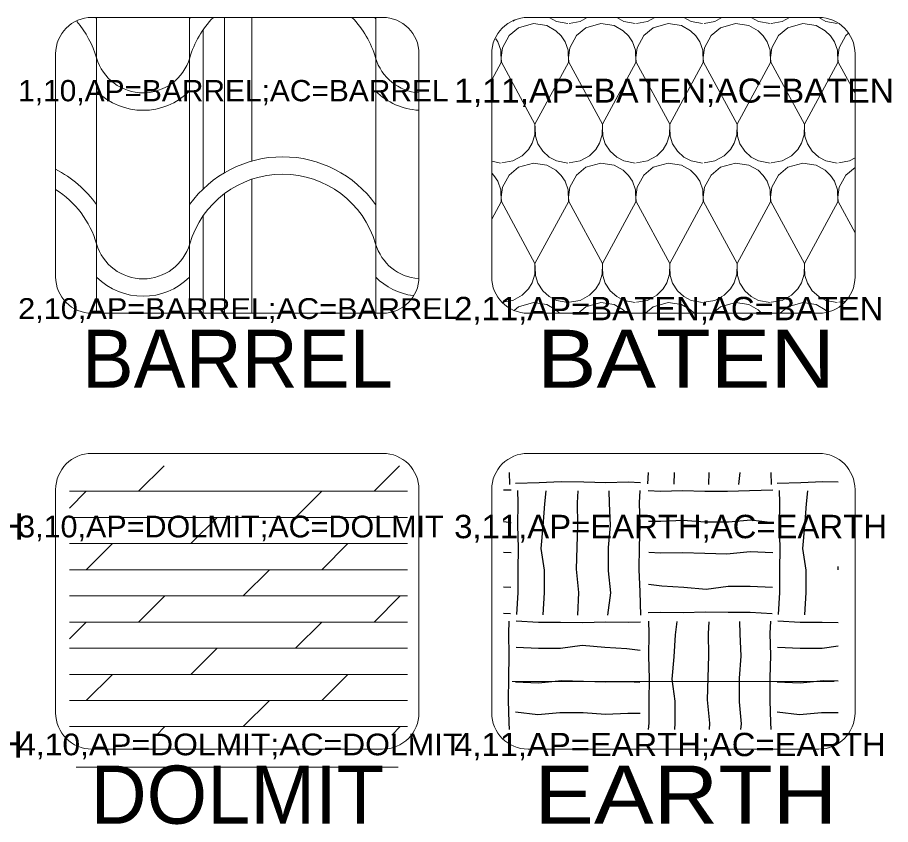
# Model space of a CAD drawing. Extents: x 95935 to 95946.4, y 95971.2 to 95974.7.
# Drawn here: x 95940.433 to 95941.635, y 95973.621 to 95974.732 of the extents above; entities that cross this region are included whole.
import ezdxf
from ezdxf.enums import TextEntityAlignment as Align

# ---------------------------------------------------------------- set-up
doc = ezdxf.new("R2010")
doc.units = 0
doc.header["$LTSCALE"] = 0.013
for name, color, linetype, lineweight in [('1', 7, 'Continuous', 13), ('25', 7, 'Continuous', 13), ('6', 7, 'Continuous', 13), ('63', 7, 'Continuous', 13)]:
    doc.layers.add(name, color=color, linetype=linetype, lineweight=lineweight)
doc.layers.add('20', color=7, linetype='Continuous')

msp = doc.modelspace()

# ---------------------------------------------------------------- linework, layer by layer
at = {"layer": '1'}
for p, q in [((95940.5357, 95974.7318), (95940.9357, 95974.7318)), ((95941.1357, 95974.7318), (95941.5357, 95974.7318)), ((95940.4857, 95974.3747), (95940.4857, 95974.6818)), ((95940.9857, 95974.6818), (95940.9857, 95974.3747)), ((95941.0857, 95974.3747), (95941.0857, 95974.6818)), ((95941.5857, 95974.6818), (95941.5857, 95974.3747)), ((95940.9357, 95974.3247), (95940.5357, 95974.3247)), ((95941.5357, 95974.3247), (95941.1357, 95974.3247)), ((95940.5357, 95974.1318), (95940.9357, 95974.1318)), ((95941.1357, 95974.1318), (95941.5357, 95974.1318)), ((95940.4857, 95973.7747), (95940.4857, 95974.0818)), ((95940.9857, 95974.0818), (95940.9857, 95973.7747)), ((95941.0857, 95973.7747), (95941.0857, 95974.0818)), ((95941.5857, 95974.0818), (95941.5857, 95973.7747)), ((95940.9357, 95973.7247), (95940.5357, 95973.7247)), ((95941.5357, 95973.7247), (95941.1357, 95973.7247))]:
    msp.add_line(p, q, dxfattribs=at)
for centre, start, end in [((95940.5357, 95974.6818), 90, 180), ((95940.9357, 95974.6818), 0, 90), ((95941.1357, 95974.6818), 90, 180), ((95941.5357, 95974.6818), 0, 90), ((95940.5357, 95974.3747), 180, 270), ((95940.9357, 95974.3747), 270, 0), ((95941.1357, 95974.3747), 180, 270), ((95941.5357, 95974.3747), 270, 0), ((95940.5357, 95974.0818), 90, 180), ((95940.9357, 95974.0818), 0, 90), ((95941.1357, 95974.0818), 90, 180), ((95941.5357, 95974.0818), 0, 90), ((95940.5357, 95973.7747), 180, 270), ((95940.9357, 95973.7747), 270, 0), ((95941.1357, 95973.7747), 180, 270), ((95941.5357, 95973.7747), 270, 0)]:
    msp.add_arc(centre, 0.05, start, end, dxfattribs=at)
at = {"layer": '25'}
for p, q in [((95941.5569, 95973.8178), (95941.1141, 95973.8178)), ((95940.9569, 95973.6997), (95940.5141, 95973.6997))]:
    msp.add_line(p, q, dxfattribs=at)
at = {"layer": '6'}
for p, q in [((95940.5421, 95974.348), (95940.5421, 95974.7318)), ((95940.6701, 95974.348), (95940.6701, 95974.7318)), ((95940.7181, 95974.5181), (95940.7181, 95974.7318)), ((95940.7559, 95974.5342), (95940.7559, 95974.7318)), ((95940.9261, 95974.348), (95940.9261, 95974.7318)), ((95941.1184, 95974.7284), (95941.1152, 95974.7266)), ((95940.6885, 95974.4955), (95940.6885, 95974.7146)), ((95941.098, 95974.5314), (95941.0857, 95974.5338)), ((95940.7559, 95974.348), (95940.7559, 95974.5092)), ((95940.7181, 95974.348), (95940.7181, 95974.4893)), ((95940.6885, 95974.348), (95940.6885, 95974.4586)), ((95940.5421, 95974.3247), (95940.5421, 95974.348)), ((95940.6701, 95974.3247), (95940.6701, 95974.348)), ((95940.6885, 95974.3247), (95940.6885, 95974.348)), ((95940.7181, 95974.3247), (95940.7181, 95974.348)), ((95940.7559, 95974.3247), (95940.7559, 95974.348)), ((95940.9261, 95974.3247), (95940.9261, 95974.348)), ((95941.5725, 95974.3414), (95941.5632, 95974.3397)), ((95940.5999, 95974.0796), (95940.6349, 95974.1146)), ((95940.9239, 95974.0796), (95940.9589, 95974.1146)), ((95940.5048, 95974.0796), (95940.97, 95974.0796)), ((95940.5048, 95974.0565), (95940.5279, 95974.0796)), ((95940.8159, 95974.0436), (95940.8519, 95974.0796)), ((95940.5048, 95974.0436), (95940.97, 95974.0436)), ((95940.5048, 95974.0436), (95940.97, 95974.0436)), ((95940.6719, 95974.0076), (95940.7079, 95974.0436)), ((95940.5048, 95974.0076), (95940.97, 95974.0076)), ((95940.5279, 95973.9716), (95940.5639, 95974.0076)), ((95940.8519, 95973.9716), (95940.8879, 95974.0076)), ((95940.5048, 95973.9716), (95940.97, 95973.9716)), ((95940.7439, 95973.9356), (95940.7799, 95973.9716)), ((95940.5048, 95973.9356), (95940.97, 95973.9356)), ((95940.5999, 95973.8996), (95940.6359, 95973.9356)), ((95940.9239, 95973.8996), (95940.9599, 95973.9356)), ((95940.5048, 95973.8996), (95940.97, 95973.8996)), ((95940.5048, 95973.8765), (95940.5279, 95973.8996)), ((95940.8159, 95973.8636), (95940.8519, 95973.8996)), ((95940.5048, 95973.8636), (95940.97, 95973.8636)), ((95940.5048, 95973.8636), (95940.97, 95973.8636)), ((95940.6719, 95973.8276), (95940.7079, 95973.8636)), ((95940.5048, 95973.8276), (95940.97, 95973.8276)), ((95940.5279, 95973.7916), (95940.5639, 95973.8276)), ((95940.8519, 95973.7916), (95940.8879, 95973.8276)), ((95940.5048, 95973.7916), (95940.97, 95973.7916)), ((95940.7439, 95973.7556), (95940.7799, 95973.7916)), ((95940.5048, 95973.7556), (95940.97, 95973.7556)), ((95940.6243, 95973.744), (95940.6359, 95973.7556)), ((95940.9483, 95973.744), (95940.9599, 95973.7556))]:
    msp.add_line(p, q, dxfattribs=at)
at = {"layer": '6', "lineweight": 25}
for p, q in [((95941.1109, 95974.0891), (95941.1104, 95974.1056)), ((95941.3005, 95974.09), (95941.3014, 95974.1056)), ((95941.3366, 95974.0896), (95941.3375, 95974.1056)), ((95941.3844, 95974.0891), (95941.3851, 95974.1056)), ((95941.4257, 95974.0891), (95941.4278, 95974.1056)), ((95941.4709, 95974.0891), (95941.4704, 95974.1056)), ((95941.1127, 95974.0813), (95941.102, 95974.081)), ((95941.1127, 95974.0361), (95941.102, 95974.0375)), ((95941.1127, 95973.9948), (95941.102, 95973.9952)), ((95941.1122, 95973.947), (95941.102, 95973.9476)), ((95941.1118, 95973.9109), (95941.102, 95973.9114))]:
    msp.add_line(p, q, dxfattribs=at)
at = {"layer": '6'}
for points in [[(95941.1907, 95974.7234), (95941.175, 95974.7264), (95941.165, 95974.7316), (95941.1648, 95974.7318)], [(95941.2173, 95974.7318), (95941.2075, 95974.7264), (95941.1925, 95974.7237)], [(95941.2833, 95974.7234), (95941.2676, 95974.7264), (95941.2577, 95974.7316), (95941.2575, 95974.7318)], [(95941.31, 95974.7318), (95941.3002, 95974.7264), (95941.2852, 95974.7237)], [(95941.376, 95974.7234), (95941.3603, 95974.7264), (95941.3503, 95974.7316), (95941.3501, 95974.7318)], [(95941.4026, 95974.7318), (95941.3928, 95974.7264), (95941.3779, 95974.7237)], [(95941.4687, 95974.7234), (95941.453, 95974.7264), (95941.443, 95974.7316), (95941.4428, 95974.7318)], [(95941.4953, 95974.7318), (95941.4855, 95974.7264), (95941.4705, 95974.7237)], [(95941.5613, 95974.7234), (95941.5456, 95974.7264), (95941.5357, 95974.7316), (95941.5355, 95974.7318)], [(95941.1907, 95974.5314), (95941.175, 95974.5344), (95941.165, 95974.5396), (95941.156, 95974.5477), (95941.1494, 95974.5579), (95941.1458, 95974.5684), (95941.1457, 95974.5802), (95941.1453, 95974.5849), (95941.1914, 95974.67), (95941.1909, 95974.6866), (95941.1867, 95974.6983), (95941.1814, 95974.7063), (95941.1742, 95974.7134), (95941.1615, 95974.7206), (95941.1431, 95974.7234), (95941.1225, 95974.7175), (95941.1096, 95974.7068), (95941.1006, 95974.6902), (95941.0987, 95974.6766), (95941.0992, 95974.6703), (95941.1453, 95974.5849), (95941.1451, 95974.5703), (95941.1413, 95974.5586), (95941.1363, 95974.5502), (95941.1275, 95974.5414), (95941.1148, 95974.5344), (95941.0999, 95974.5317)], [(95941.2833, 95974.5314), (95941.2676, 95974.5344), (95941.2577, 95974.5396), (95941.2487, 95974.5477), (95941.2421, 95974.5579), (95941.2385, 95974.5684), (95941.2383, 95974.5802), (95941.238, 95974.5849), (95941.284, 95974.67), (95941.2835, 95974.6866), (95941.2793, 95974.6983), (95941.274, 95974.7063), (95941.2668, 95974.7134), (95941.2542, 95974.7206), (95941.2358, 95974.7234), (95941.2152, 95974.7175), (95941.2022, 95974.7068), (95941.1933, 95974.6902), (95941.1914, 95974.6766), (95941.1918, 95974.6703), (95941.238, 95974.5849), (95941.2378, 95974.5703), (95941.234, 95974.5586), (95941.2289, 95974.5502), (95941.2202, 95974.5414), (95941.2075, 95974.5344), (95941.1925, 95974.5317)], [(95941.376, 95974.5314), (95941.3603, 95974.5344), (95941.3503, 95974.5396), (95941.3414, 95974.5477), (95941.3347, 95974.5579), (95941.3312, 95974.5684), (95941.331, 95974.5802), (95941.3307, 95974.5849), (95941.3767, 95974.67), (95941.3762, 95974.6866), (95941.372, 95974.6983), (95941.3667, 95974.7063), (95941.3595, 95974.7134), (95941.3469, 95974.7206), (95941.3285, 95974.7234), (95941.3079, 95974.7175), (95941.2949, 95974.7068), (95941.286, 95974.6902), (95941.284, 95974.6766), (95941.2845, 95974.6703), (95941.3307, 95974.5849), (95941.3304, 95974.5703), (95941.3267, 95974.5586), (95941.3216, 95974.5502), (95941.3129, 95974.5414), (95941.3002, 95974.5344), (95941.2852, 95974.5317)], [(95941.4687, 95974.5314), (95941.453, 95974.5344), (95941.443, 95974.5396), (95941.4341, 95974.5477), (95941.4274, 95974.5579), (95941.4238, 95974.5684), (95941.4237, 95974.5802), (95941.4233, 95974.5849), (95941.4694, 95974.67), (95941.4689, 95974.6866), (95941.4647, 95974.6983), (95941.4594, 95974.7063), (95941.4522, 95974.7134), (95941.4395, 95974.7206), (95941.4211, 95974.7234), (95941.4005, 95974.7175), (95941.3876, 95974.7068), (95941.3786, 95974.6902), (95941.3767, 95974.6766), (95941.3772, 95974.6703), (95941.4233, 95974.5849), (95941.4231, 95974.5703), (95941.4193, 95974.5586), (95941.4143, 95974.5502), (95941.4055, 95974.5414), (95941.3928, 95974.5344), (95941.3779, 95974.5317)], [(95941.5613, 95974.5314), (95941.5456, 95974.5344), (95941.5357, 95974.5396), (95941.5267, 95974.5477), (95941.5201, 95974.5579), (95941.5165, 95974.5684), (95941.5163, 95974.5802), (95941.516, 95974.5849), (95941.562, 95974.67), (95941.5615, 95974.6866), (95941.5573, 95974.6983), (95941.552, 95974.7063), (95941.5448, 95974.7134), (95941.5322, 95974.7206), (95941.5138, 95974.7234), (95941.4932, 95974.7175), (95941.4802, 95974.7068), (95941.4713, 95974.6902), (95941.4694, 95974.6766), (95941.4698, 95974.6703), (95941.516, 95974.5849), (95941.5158, 95974.5703), (95941.512, 95974.5586), (95941.5069, 95974.5502), (95941.4982, 95974.5414), (95941.4855, 95974.5344), (95941.4705, 95974.5317)], [(95941.0857, 95974.646), (95941.0987, 95974.67), (95941.0982, 95974.6866), (95941.094, 95974.6983), (95941.0912, 95974.7026)], [(95941.5762, 95974.7095), (95941.5729, 95974.7068), (95941.564, 95974.6902), (95941.562, 95974.6766), (95941.5625, 95974.6703), (95941.5857, 95974.6274)], [(95941.5857, 95974.5385), (95941.5782, 95974.5344), (95941.5632, 95974.5317)], [(95941.1907, 95974.3394), (95941.175, 95974.3424), (95941.165, 95974.3476), (95941.156, 95974.3557), (95941.1494, 95974.3659), (95941.1458, 95974.3764), (95941.1457, 95974.3882), (95941.1453, 95974.3929), (95941.1914, 95974.478), (95941.1909, 95974.4946), (95941.1867, 95974.5063), (95941.1814, 95974.5143), (95941.1742, 95974.5214), (95941.1615, 95974.5286), (95941.1431, 95974.5314), (95941.1225, 95974.5255), (95941.1096, 95974.5148), (95941.1006, 95974.4982), (95941.0987, 95974.4846), (95941.0992, 95974.4783), (95941.1453, 95974.3929), (95941.1451, 95974.3783), (95941.1413, 95974.3666), (95941.1363, 95974.3582), (95941.1275, 95974.3494), (95941.1148, 95974.3424), (95941.0999, 95974.3397)], [(95941.2833, 95974.3394), (95941.2676, 95974.3424), (95941.2577, 95974.3476), (95941.2487, 95974.3557), (95941.2421, 95974.3659), (95941.2385, 95974.3764), (95941.2383, 95974.3882), (95941.238, 95974.3929), (95941.284, 95974.478), (95941.2835, 95974.4946), (95941.2793, 95974.5063), (95941.274, 95974.5143), (95941.2668, 95974.5214), (95941.2542, 95974.5286), (95941.2358, 95974.5314), (95941.2152, 95974.5255), (95941.2022, 95974.5148), (95941.1933, 95974.4982), (95941.1914, 95974.4846), (95941.1918, 95974.4783), (95941.238, 95974.3929), (95941.2378, 95974.3783), (95941.234, 95974.3666), (95941.2289, 95974.3582), (95941.2202, 95974.3494), (95941.2075, 95974.3424), (95941.1925, 95974.3397)], [(95941.376, 95974.3394), (95941.3603, 95974.3424), (95941.3503, 95974.3476), (95941.3414, 95974.3557), (95941.3347, 95974.3659), (95941.3312, 95974.3764), (95941.331, 95974.3882), (95941.3307, 95974.3929), (95941.3767, 95974.478), (95941.3762, 95974.4946), (95941.372, 95974.5063), (95941.3667, 95974.5143), (95941.3595, 95974.5214), (95941.3469, 95974.5286), (95941.3285, 95974.5314), (95941.3079, 95974.5255), (95941.2949, 95974.5148), (95941.286, 95974.4982), (95941.284, 95974.4846), (95941.2845, 95974.4783), (95941.3307, 95974.3929), (95941.3304, 95974.3783), (95941.3267, 95974.3666), (95941.3216, 95974.3582), (95941.3129, 95974.3494), (95941.3002, 95974.3424), (95941.2852, 95974.3397)], [(95941.4687, 95974.3394), (95941.453, 95974.3424), (95941.443, 95974.3476), (95941.4341, 95974.3557), (95941.4274, 95974.3659), (95941.4238, 95974.3764), (95941.4237, 95974.3882), (95941.4233, 95974.3929), (95941.4694, 95974.478), (95941.4689, 95974.4946), (95941.4647, 95974.5063), (95941.4594, 95974.5143), (95941.4522, 95974.5214), (95941.4395, 95974.5286), (95941.4211, 95974.5314), (95941.4005, 95974.5255), (95941.3876, 95974.5148), (95941.3786, 95974.4982), (95941.3767, 95974.4846), (95941.3772, 95974.4783), (95941.4233, 95974.3929), (95941.4231, 95974.3783), (95941.4193, 95974.3666), (95941.4143, 95974.3582), (95941.4055, 95974.3494), (95941.3928, 95974.3424), (95941.3779, 95974.3397)], [(95941.5613, 95974.3394), (95941.5456, 95974.3424), (95941.5357, 95974.3476), (95941.5267, 95974.3557), (95941.5201, 95974.3659), (95941.5165, 95974.3764), (95941.5163, 95974.3882), (95941.516, 95974.3929), (95941.562, 95974.478), (95941.5615, 95974.4946), (95941.5573, 95974.5063), (95941.552, 95974.5143), (95941.5448, 95974.5214), (95941.5322, 95974.5286), (95941.5138, 95974.5314), (95941.4932, 95974.5255), (95941.4802, 95974.5148), (95941.4713, 95974.4982), (95941.4694, 95974.4846), (95941.4698, 95974.4783), (95941.516, 95974.3929), (95941.5158, 95974.3783), (95941.512, 95974.3666), (95941.5069, 95974.3582), (95941.4982, 95974.3494), (95941.4855, 95974.3424), (95941.4705, 95974.3397)], [(95941.5857, 95974.5253), (95941.5729, 95974.5148), (95941.564, 95974.4982), (95941.562, 95974.4846), (95941.5625, 95974.4783), (95941.5857, 95974.4354)], [(95941.0857, 95974.454), (95941.0987, 95974.478), (95941.0982, 95974.4946), (95941.094, 95974.5063), (95941.0887, 95974.5143), (95941.0857, 95974.5173)], [(95941.179, 95974.3247), (95941.1742, 95974.3294), (95941.1615, 95974.3366), (95941.1431, 95974.3394), (95941.1225, 95974.3335), (95941.1165, 95974.3285)], [(95941.2716, 95974.3247), (95941.2668, 95974.3294), (95941.2542, 95974.3366), (95941.2358, 95974.3394), (95941.2152, 95974.3335), (95941.2045, 95974.3247)], [(95941.3643, 95974.3247), (95941.3595, 95974.3294), (95941.3469, 95974.3366), (95941.3285, 95974.3394), (95941.3079, 95974.3335), (95941.2972, 95974.3247)], [(95941.457, 95974.3247), (95941.4522, 95974.3294), (95941.4395, 95974.3366), (95941.4211, 95974.3394), (95941.4005, 95974.3335), (95941.3899, 95974.3247)], [(95941.5472, 95974.327), (95941.5448, 95974.3294), (95941.5322, 95974.3366), (95941.5138, 95974.3394), (95941.4932, 95974.3335), (95941.4825, 95974.3247)]]:
    msp.add_lwpolyline(points, dxfattribs=at)
at = {"layer": '6', "lineweight": 25}
for points in [[(95941.1187, 95974.0909), (95941.1509, 95974.0918), (95941.1813, 95974.0931), (95941.2126, 95974.0927), (95941.243, 95974.0918), (95941.2735, 95974.0927), (95941.2904, 95974.0918)], [(95941.4787, 95974.0909), (95941.5109, 95974.0918), (95941.5413, 95974.0931), (95941.5627, 95974.0928)], [(95941.1205, 95973.91), (95941.1222, 95973.9404), (95941.1222, 95973.9709), (95941.1227, 95974.0017), (95941.1218, 95974.0326), (95941.1222, 95974.0639), (95941.1218, 95974.0808)], [(95941.1566, 95973.9096), (95941.1583, 95973.9404), (95941.1583, 95973.9709), (95941.154, 95974.0008), (95941.1566, 95974.0317), (95941.1587, 95974.0621), (95941.1609, 95974.0804)], [(95941.2044, 95973.9091), (95941.2057, 95973.9404), (95941.2026, 95973.9726), (95941.2035, 95974.0026), (95941.2044, 95974.0334), (95941.2039, 95974.0639), (95941.2048, 95974.08)], [(95941.2457, 95973.9091), (95941.2496, 95973.9396), (95941.2465, 95973.97), (95941.2465, 95974.0022), (95941.2491, 95974.0326), (95941.2478, 95974.0634), (95941.2474, 95974.0804)], [(95941.2909, 95973.9091), (95941.29, 95973.9413), (95941.2887, 95973.9717), (95941.2891, 95974.003), (95941.29, 95974.0334), (95941.2891, 95974.0639), (95941.29, 95974.0808)], [(95941.4727, 95974.0813), (95941.4405, 95974.0804), (95941.4101, 95974.0791), (95941.3788, 95974.0795), (95941.3484, 95974.0804), (95941.3179, 95974.0795), (95941.301, 95974.0804)], [(95941.4805, 95973.91), (95941.4822, 95973.9404), (95941.4822, 95973.9709), (95941.4827, 95974.0017), (95941.4818, 95974.0326), (95941.4822, 95974.0639), (95941.4818, 95974.0808)], [(95941.5166, 95973.9096), (95941.5183, 95973.9404), (95941.5183, 95973.9709), (95941.514, 95974.0008), (95941.5166, 95974.0317), (95941.5187, 95974.0621), (95941.5209, 95974.0804)], [(95941.4727, 95974.0361), (95941.4422, 95974.04), (95941.4118, 95974.0369), (95941.3796, 95974.0369), (95941.3492, 95974.0395), (95941.3184, 95974.0382), (95941.3014, 95974.0378)], [(95941.4727, 95973.9948), (95941.4414, 95973.9961), (95941.4092, 95973.993), (95941.3792, 95973.9939), (95941.3484, 95973.9948), (95941.3179, 95973.9943), (95941.3019, 95973.9952)], [(95941.5627, 95973.9716), (95941.5626, 95973.9726), (95941.5627, 95973.9759)], [(95941.4722, 95973.947), (95941.4414, 95973.9487), (95941.4109, 95973.9487), (95941.381, 95973.9444), (95941.3501, 95973.947), (95941.3197, 95973.9491), (95941.3014, 95973.9513)], [(95941.4718, 95973.9109), (95941.4414, 95973.9126), (95941.4109, 95973.9126), (95941.3801, 95973.9131), (95941.3492, 95973.9122), (95941.3179, 95973.9126), (95941.301, 95973.9122)], [(95941.1103, 95973.7517), (95941.11, 95973.7613), (95941.1087, 95973.7917), (95941.1091, 95973.823), (95941.11, 95973.8534), (95941.1091, 95973.8839), (95941.11, 95973.9008)], [(95941.1196, 95973.9013), (95941.15, 95973.8996), (95941.1805, 95973.8996), (95941.2113, 95973.8991), (95941.2422, 95973.9), (95941.2735, 95973.8996), (95941.2904, 95973.9)], [(95941.3017, 95973.7517), (95941.3022, 95973.7604), (95941.3022, 95973.7909), (95941.3027, 95973.8217), (95941.3018, 95973.8526), (95941.3022, 95973.8839), (95941.3018, 95973.9008)], [(95941.3378, 95973.7517), (95941.3383, 95973.7604), (95941.3383, 95973.7909), (95941.334, 95973.8208), (95941.3366, 95973.8517), (95941.3387, 95973.8821), (95941.3409, 95973.9004)], [(95941.3853, 95973.7517), (95941.3857, 95973.7604), (95941.3826, 95973.7926), (95941.3835, 95973.8226), (95941.3844, 95973.8534), (95941.3839, 95973.8839), (95941.3848, 95973.9)], [(95941.4286, 95973.7517), (95941.4296, 95973.7596), (95941.4265, 95973.79), (95941.4265, 95973.8222), (95941.4291, 95973.8526), (95941.4278, 95973.8834), (95941.4274, 95973.9004)], [(95941.4703, 95973.7517), (95941.47, 95973.7613), (95941.4687, 95973.7917), (95941.4691, 95973.823), (95941.47, 95973.8534), (95941.4691, 95973.8839), (95941.47, 95973.9008)], [(95941.4796, 95973.9013), (95941.51, 95973.8996), (95941.5405, 95973.8996), (95941.5627, 95973.8992)], [(95941.1192, 95973.8652), (95941.15, 95973.8635), (95941.1805, 95973.8635), (95941.2104, 95973.8679), (95941.2413, 95973.8652), (95941.2717, 95973.8631), (95941.29, 95973.8609)], [(95941.4792, 95973.8652), (95941.51, 95973.8635), (95941.5405, 95973.8635), (95941.5627, 95973.8668)], [(95941.1187, 95973.8174), (95941.15, 95973.8161), (95941.1822, 95973.8192), (95941.2122, 95973.8183), (95941.243, 95973.8174), (95941.2735, 95973.8179), (95941.2896, 95973.817)], [(95941.4787, 95973.8174), (95941.51, 95973.8161), (95941.5422, 95973.8192), (95941.5627, 95973.8186)], [(95941.1187, 95973.7761), (95941.1492, 95973.7722), (95941.1796, 95973.7753), (95941.2118, 95973.7753), (95941.2422, 95973.7727), (95941.273, 95973.774), (95941.29, 95973.7744)], [(95941.4787, 95973.7761), (95941.5092, 95973.7722), (95941.5396, 95973.7753), (95941.5627, 95973.7753)]]:
    msp.add_lwpolyline(points, dxfattribs=at)
at = {"layer": '6'}
for centre, radius, start, end in [((95940.4141, 95974.6387), 0.1333, 16.2602, 40.9972), ((95940.4141, 95974.6387), 0.1573, 35.5548, 36.2973), ((95940.7981, 95974.6387), 0.1333, 135.6908, 163.7398), ((95940.7981, 95974.6387), 0.1573, 143.7027, 144.4452), ((95940.7981, 95974.6387), 0.1333, 16.2602, 44.3092), ((95940.7981, 95974.6387), 0.1573, 35.5548, 36.2973), ((95940.6061, 95974.6947), 0.0667, 196.2602, 343.7398), ((95940.9901, 95974.6947), 0.0667, 196.2602, 266.2157), ((95940.6061, 95974.6947), 0.0907, 225.0991, 314.9009), ((95940.9901, 95974.6947), 0.0907, 225.0991, 267.2184), ((95940.7981, 95974.3827), 0.1573, 35.5548, 144.4452), ((95940.4141, 95974.3827), 0.1573, 35.5548, 62.9296), ((95940.7981, 95974.3827), 0.1333, 16.2602, 163.7398), ((95940.4141, 95974.3827), 0.1333, 16.2602, 57.5204), ((95940.6061, 95974.4387), 0.0667, 196.2602, 343.7398), ((95940.9901, 95974.4387), 0.0667, 196.2602, 265.7832), ((95940.6061, 95974.4387), 0.0907, 225.0991, 314.9009), ((95940.9901, 95974.4387), 0.0907, 225.0991, 261.9794)]:
    msp.add_arc(centre, radius, start, end, dxfattribs=at)

# ---------------------------------------------------------------- texts
at = {"layer": '20'}
for s, p in [('BARREL', (95940.7358, 95974.222)), ('DOLMIT', (95940.7358, 95973.622))]:
    msp.add_text(s, height=0.08, dxfattribs=at).set_placement(p, align=Align.CENTER)
at = {"layer": '20', "width": 1.15}
for s, p in [(' BATEN', (95941.3359, 95974.222)), (' EARTH', (95941.3358, 95973.622))]:
    msp.add_text(s, height=0.08, dxfattribs=at).set_placement(p, align=Align.CENTER)
at = {"layer": '63'}
for s, height, width, p in [('1,10,AP=BARREL;AC=BARREL', 0.0293, 1.05, (95940.4341, 95974.6164)), ('1,11,AP=BATEN;AC=BATEN', 0.033, 1.05, (95941.0341, 95974.6146)), ('2,10,AP=BARREL;AC=BARREL', 0.0287, 1.1, (95940.4341, 95974.3167)), ('2,11,AP=BATEN;AC=BATEN', 0.0322, 1.05, (95941.0341, 95974.315)), ('3,9,AP=DASH;AC=DASH', 0.0363, 1.1, (95939.8341, 95974.0129)), ('3,10,AP=DOLMIT;AC=DOLMIT', 0.0299, 1.05, (95940.4341, 95974.0161)), ('3,11,AP=EARTH;AC=EARTH', 0.0322, 1.05, (95941.0341, 95974.015)), ('4,9,AP=DASH;AC=DASH', 0.0362, 1.1, (95939.8341, 95973.713)), ('4,10,AP=DOLMIT;AC=DOLMIT', 0.0298, 1.1, (95940.4341, 95973.7162)), ('4,11,AP=EARTH;AC=EARTH', 0.0321, 1.05, (95941.0341, 95973.715))]:
    msp.add_text(s, height=height, dxfattribs=dict(at, width=width)).set_placement(p)

doc.saveas('drawing.dxf')
